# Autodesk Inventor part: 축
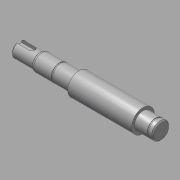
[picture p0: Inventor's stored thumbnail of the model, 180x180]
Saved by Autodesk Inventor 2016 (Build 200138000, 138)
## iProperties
Created: 2015-12
Part Number: 축
Material: 강철, 연강
Document SubType Name: Modeling
Designer: mduedu
Density: 7.86 g/cm^3
Appearance: 강철
Author: mduedu
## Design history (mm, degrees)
sketch "스케치1"
  geometry: L1 (-62.5, 0)-(62.5, 0); L2 (-62.5, 0)-(-62.5, 6.5); L3 (-62.5, 6.5)-(-43.5, 6.5); L4 (-43.5, 7)-(-42.634, 7.5); L5 (-42.634, 7.5)-(-9.5, 7.5); L6 (-9.5, 7.5)-(-9.5, 10); L7 (-9.5, 10)-(46.5, 10); L8 (46.5, 10)-(46.5, 7.5); L9 (46.5, 7.5)-(62.5, 7.5); L10 (62.5, 7.5)-(62.5, 0); L11 (-43.5, 6.5)-(-43.5, 7); 2 further points
  constraints: 22 end point, 6 parallel, 2 perpendicular, 1 coincident, 1 horizontal, 1 midpoint, 1 vertical
  dimensions: "d0" = 13 diameter of L3 L1; "d2" = 15 diameter of L5 L1; "d3" = 20 diameter of L7 L1; "d5" = 15 diameter of L9 L1; "d6" = 125 distance of L1.start L1.end; "d7" = 19 distance of L2.end L3.end; "d8" = 34 distance from line of L6 L3.end; "d9" = 56 distance of L6.end L7.end; "d41" = 14 diameter of L4.start L1; "d42" = 30 deg angle of L4 L3
revolve "회전1" sketch "스케치1" stored, may be unused: angle "d11" = 90 deg
node "작업 평면1"
node "작업 평면2"
sketch "스케치3"
  geometry: L1 (9.5, -2.5)-(-2.5, -2.5); L2 (-2.5, 2.5)-(9.5, 2.5); L3 (9.5, 2.5)-(9.5, -2.5); L4 (9.5, 6.5)-(9.5, -6.5) reference; A1 r 2.5 centre (-2.5, 0) between (-2.5, 2.5) and (-2.5, -2.5); 1 further point
  constraints: 6 end point, 2 point on circle, 2 tangent, 1 centre point, 1 collinear, 1 horizontal, 1 horizontal alignment, 1 parallel
  dimensions: "d17" = 5 distance of L2.end L1.start; "d19" = 12 distance from line of A1.centre L3
extrude "돌출2" cut sketch "스케치3" distance "d20" = 3; taper "d21" = 0 deg
chamfer "모따기1" distance "d22" = 1; stored, may be unused: second distance "d23" = 2, angle "d24" = 45 deg
fillet "모깎기1" dims "d25" = 3
sketch "스케치4"
  geometry: L1 (-9.5, -10)-(-9.5, 10) reference; L2 (-9.5, 0)-(0, 0); L3 (-26.65, 12.15)-(-25.5, 12.15); L4 (-25.5, 12.15)-(-25.5, 7.15); L5 (-25.5, 7.15)-(-26.65, 7.15); L6 (-26.65, 7.15)-(-26.65, 12.15); L7 (57.5, 12.15)-(58.65, 12.15); L8 (58.65, 12.15)-(58.65, 7.15); L9 (58.65, 7.15)-(57.5, 7.15); L10 (57.5, 7.15)-(57.5, 12.15); L11 (62.5, -7.5)-(62.5, 7.5) reference
  constraints: 18 end point, 4 parallel, 2 horizontal, 2 perpendicular, 1 midpoint
  dimensions: "d26" = 16 distance between parallel lines of L4 L1; "d27" = 1.15 distance of L3.start L3.end; "d28" = 14.3 diameter of L5 L2; "d29" = 5 distance of L3.end L4.end; "d30" = 1.15 distance of L7.start L7.end; "d31" = 5 distance of L7.end L8.end; "d32" = 5 distance between parallel lines of L10 L11; "d33" = 14.3 diameter of L9 L2
revolve "회전2" sketch "스케치4" stored, may be unused: angle "d34" = 90 deg
chamfer "모따기2" distance "d35" = 1; stored, may be unused: second distance "d36" = 2, angle "d37" = 45 deg
sketch "스케치5"
  geometry: 2 further points
  constraints: 1 coincident
sketch "스케치6"
  geometry: 1 further point
hole "구멍1" sketch "스케치6" at (2.5, -3.5) diameter "d43" = 4.917; stored, may be unused: countersink angle "d47" = 90 deg, drill point angle "d49" = 120 deg; dims "d44" = 14, "d45" = 4, "d46" = 2, "d48" = 17
node "솔리드1"
other parameters: "d12" = -15.5
